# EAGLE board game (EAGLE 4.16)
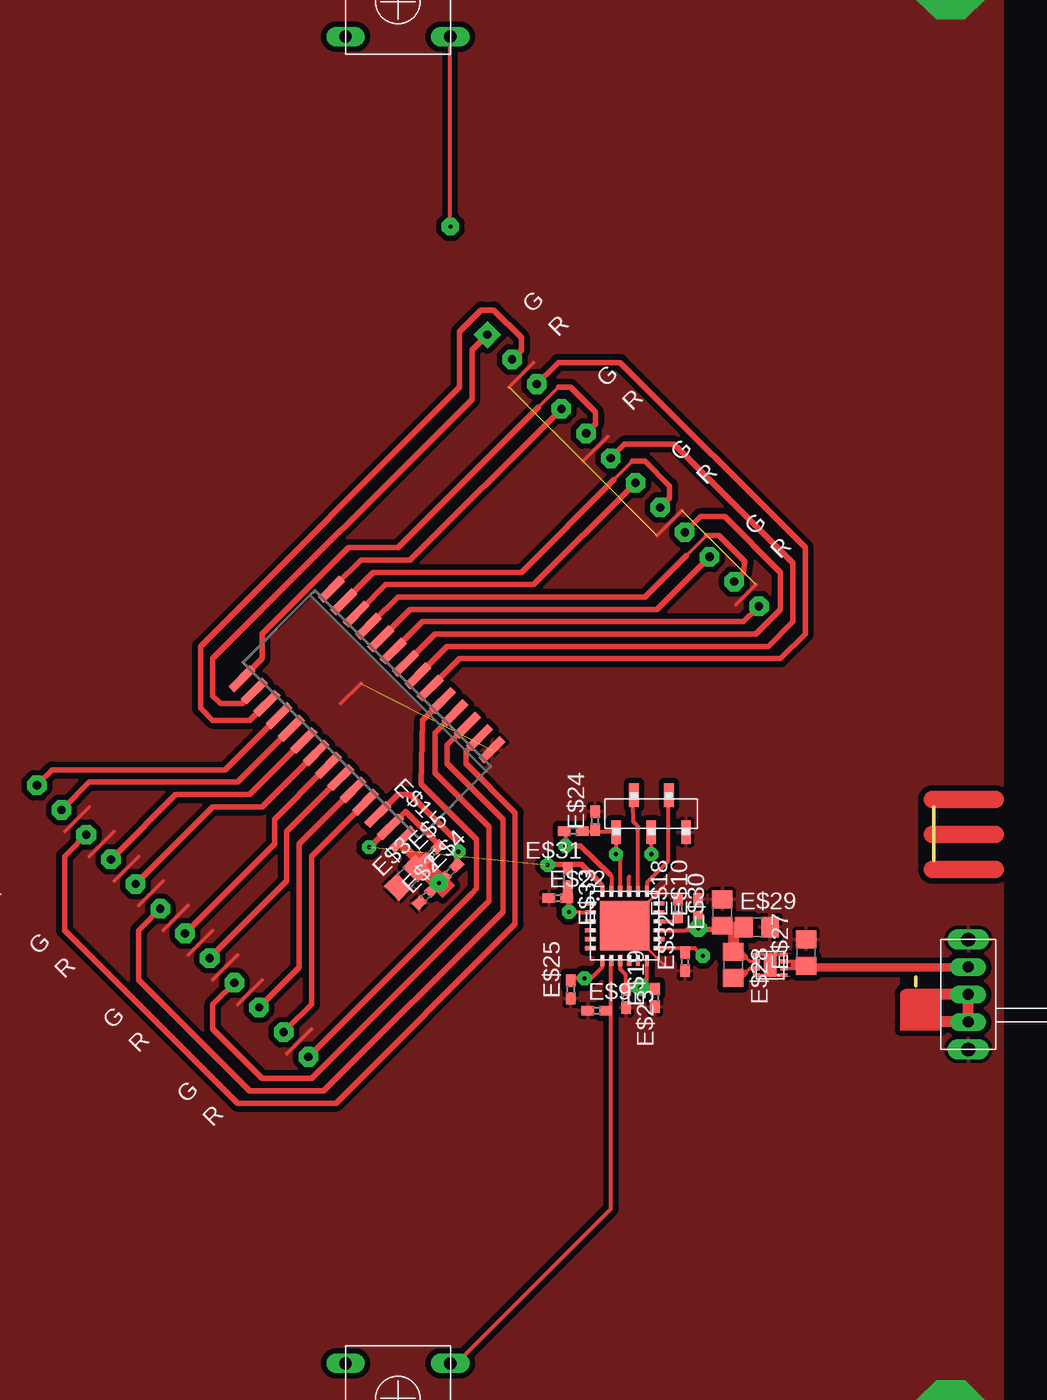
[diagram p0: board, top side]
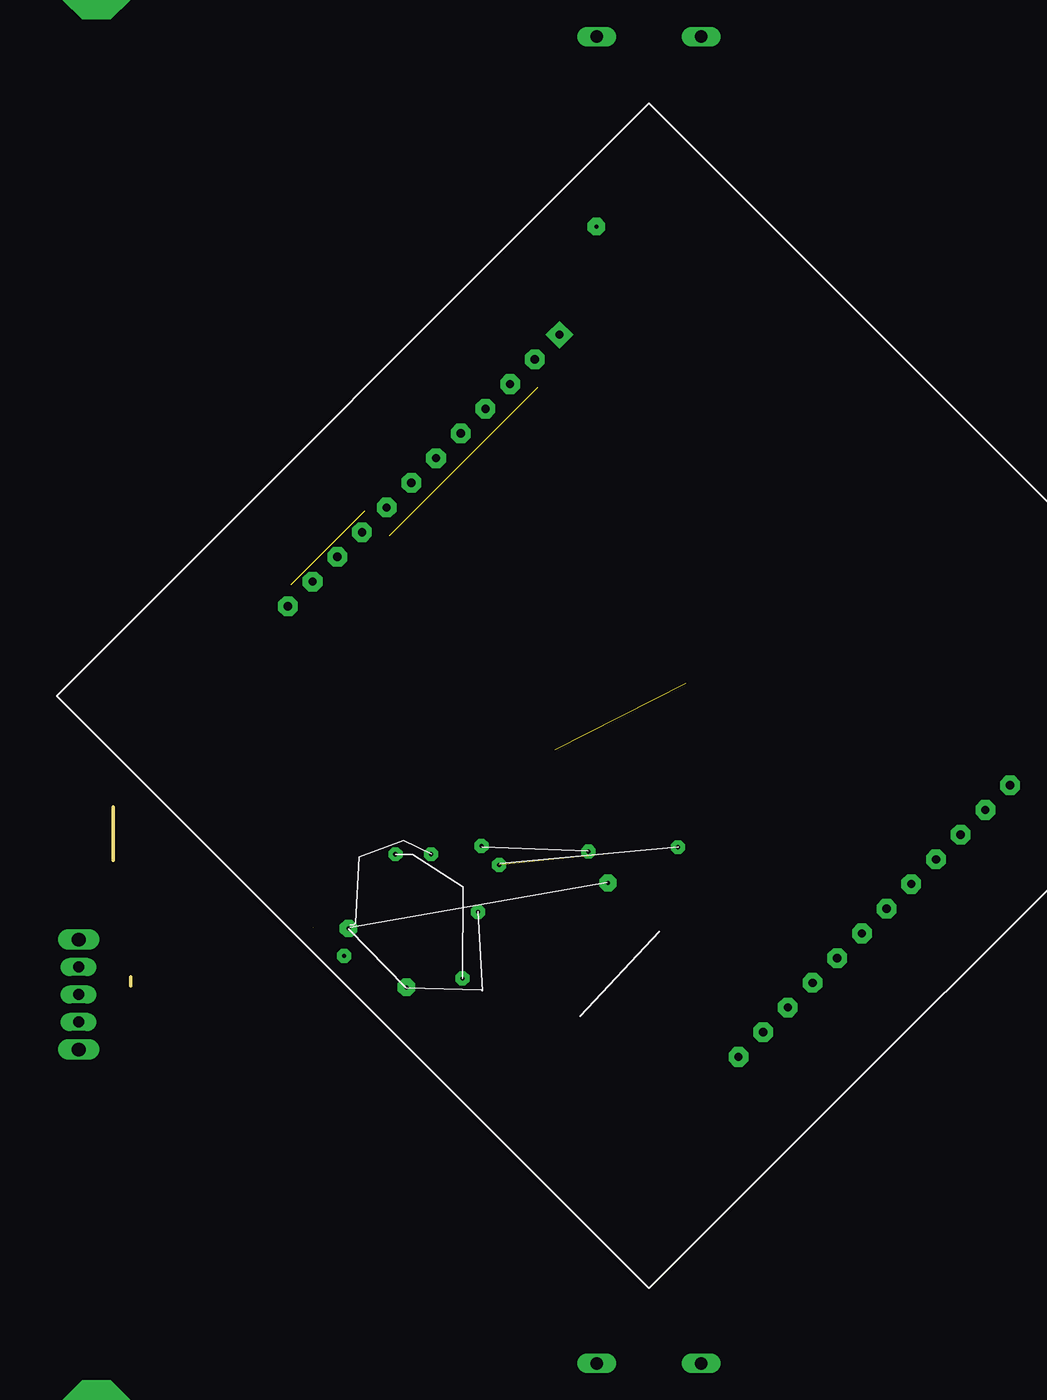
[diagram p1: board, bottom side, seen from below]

Size 1.3 x 13 mm. Coordinates in mm from the lower left corner, seen from the top.
Outline: 1.3,13 1.3,9.1
Outline: 0,0.65 0,0
Copper layers (1*16): Top 0.035mm / dielectric 1.5mm / Bottom 0.035mm
Design rules "default": minimum track width 10mil, minimum drill 24mil, track to track 8mil, track to pad 8mil, pad to pad 8mil, via to via 8mil, smd to smd 8mil, copper to edge 40mil, drill to drill 8mil, minimum pad ring 10mil, minimum via ring 8mil, stop-mask expansion 4mil, vias tented up to drill 0mil, thermal gap 10mil

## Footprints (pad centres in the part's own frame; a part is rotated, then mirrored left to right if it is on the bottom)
SO28W = smd 0.6 x 2.2: 1 -8.255,-4.6; 2 -6.985,-4.6; 3 -5.715,-4.6; 4 -4.445,-4.6; 5 -3.175,-4.6; 6 -1.905,-4.6; 7 -0.635,-4.6; 8 0.635,-4.6; 9 1.905,-4.6; 10 3.175,-4.6; 11 4.445,-4.6; 12 5.715,-4.6; 13 6.985,-4.6; 14 8.255,-4.6; 15 8.255,4.6; 16 6.985,4.6; 17 5.715,4.6; 18 4.445,4.6; 19 3.175,4.6; 20 1.905,4.6; 21 0.635,4.6; 22 -0.635,4.6; 23 -1.905,4.6; 24 -3.175,4.6; 25 -4.445,4.6; 26 -5.715,4.6; 27 -6.985,4.6; 28 -8.255,4.6
C0402 = smd 0.9 x 0.7: 1 -0.65,0; 2 0.65,0
C0805 = smd 1.3 x 1.5: 1 -0.95,0; 2 0.95,0
SW_TACT_KSL4 = drill 0.9 long: 1 -3.81,2.54; 2 -3.81,-2.54; 3 3.81,-2.54; 4 3.81,2.54
HEADER5S = smd 0.7 x 1.7: P$1 0,1.35; P$2 2.55,1.35; P$3 -2.55,1.35; P$4 -1.3,-1.35; P$5 1.25,-1.35
SLIDER6 = drill 1 long: P$1 -4,0; P$2 4,0 | drill 0.8 long: P$3 -2,0; P$4 0,0; P$5 2,0
LC2088AURYG1C = drill 0.6 pad 1.422 square: P$1 -13.97,-23.177 | drill 0.6 pad 1.422 octagon: P$2 -11.43,-23.177; P$3 -8.89,-23.177; P$4 -6.35,-23.177; P$5 -3.81,-23.177; P$6 -1.27,-23.177; P$7 1.27,-23.177; P$8 3.81,-23.177; P$9 6.35,-23.177; P$10 8.89,-23.177; P$11 11.43,-23.177; P$12 13.97,-23.177; P$13 -13.97,23.177; P$14 -11.43,23.177; P$15 -8.89,23.177; P$16 -6.35,23.177; P$17 -3.81,23.177; P$18 -1.27,23.177; P$19 1.27,23.177; P$20 3.81,23.177; P$21 6.35,23.177; P$22 8.89,23.177; P$23 11.43,23.177; P$24 13.97,23.177
QFN24-5 = smd 0.8 x 0.3: 1 -2.5,1.625; 2 -2.5,0.975; 3 -2.5,0.325; 4 -2.5,-0.325; 5 -2.5,-0.975; 6 -2.5,-1.625; 13 2.5,-1.625; 14 2.5,-0.975; 15 2.5,-0.325; 16 2.5,0.325; 17 2.5,0.975; 18 2.5,1.625 | smd 0.3 x 0.8: 7 -1.625,-2.5; 8 -0.975,-2.5; 9 -0.325,-2.5; 10 0.325,-2.5; 11 0.975,-2.5; 12 1.625,-2.5; 19 1.625,2.5; 20 0.975,2.5; 21 0.325,2.5; 22 -0.325,2.5; 23 -0.975,2.5; 24 -1.625,2.5 | smd 3.6 x 3.6: P$29 0,0
WSON8 = smd 0.28 x 0.5: 1 -1,-1; 2 -0.5,-1; 3 0,-1; 4 0.5,-1; 5 0.5,1; 6 0,1; 7 -0.5,1; 8 -1,1 | smd 1.6 x 0.9: EP -0.25,0

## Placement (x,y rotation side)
E$1  [SO28W]  not placed on the board
E$2  [C0402]  not placed on the board
E$3  [C0805]  not placed on the board
E$4  [C0402]  not placed on the board
E$5  [C0402]  not placed on the board
E$6  [SW_TACT_KSL4]  not placed on the board
E$7  [SW_TACT_KSL4]  not placed on the board
E$8  [HEADER5S]  not placed on the board
E$9  [C0402]  not placed on the board
E$10  [C0402]  not placed on the board
E$11  [SLIDER6]  3.8,-0.65 270 top
E$13  [LC2088AURYG1C]  not placed on the board
E$17  [QFN24-5]  not placed on the board
E$18  [C0402]  not placed on the board
E$19  [C0402]  not placed on the board
E$22  [C0402]  not placed on the board
E$23  [C0402]  not placed on the board
E$24  [C0402]  not placed on the board
E$25  [C0402]  not placed on the board
E$26  [WSON8]  -10.61,1.76 90 top  (outside the outline)
E$27  [C0805]  not placed on the board
E$28  [C0805]  not placed on the board
E$29  [C0805]  not placed on the board
E$30  [C0805]  not placed on the board
E$31  [C0402]  not placed on the board
E$32  [C0402]  not placed on the board
E$33  [C0402]  not placed on the board

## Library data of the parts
E$1-E$5 E$9 E$10 E$18 E$19 E$22-E$25 E$27-E$33 = ref-packages
E$6-E$8 E$11 = sb
E$13 = display-hp
E$17 = silabs
E$26 = texas

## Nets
GND: E$1.1 E$2.1 E$3.1 E$6.1 E$6.4 E$7.2 E$7.3 E$8.P$3 E$9.1 E$10.2 E$11.P$1 E$11.P$2 E$18.2 E$19.1 E$22.1 E$23.2 E$24.2 E$25.1 E$26.1 E$26.4 E$26.5 E$26.8 E$26.EP E$27.2 E$29.2 E$30.2 E$32.1
S$30: E$26.7
S$31: E$26.6
S$32: E$26.2
S$34: E$26.3
S$74: E$11.P$4

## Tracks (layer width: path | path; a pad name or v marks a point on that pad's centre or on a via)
GND  (via drill 0.5 pad 5)  (4 unrouted)
  Top 0.2: -20.22,5.33 -18.27,7.28 | -18.27,1.43 -20.14,3.3
  Top 0.254: -51.17,0.43 -49.37,2.23 | -58.35,7.62 -56.55,9.41 | -52.96,2.23 -51.17,4.03 | -56.55,5.82 -54.76,7.62 | -61.94,11.21 -60.15,13.01 | -60.15,9.41 -58.35,11.21 | -54.76,4.03 -52.96,5.82 | -49.37,-1.36 -47.57,0.43 | -45.78,-4.96 -43.98,-3.16 | -10.61,2.26 E$26.5 | -10.61,2.26 E$26.4 | -10.61,0.76 -10.61,2.26 | -10.61,0.76 E$26.1 | E$26.8 -10.61,0.76 | -41.85,20.53 -40.39,21.99 | -13.11,27.71 -11.65,29.17 | -29.61,43.54 -27.82,45.34 | -24.23,38.15 -22.43,39.95 | -18.84,32.76 -17.04,34.56
  other vias: -77.45,72.8 2.5,72.8 -77.45,-31.2 2.5,-31.2
  pour Top (isolate 0.406): 6.28,76.66 6.28,-35.1 -81.35,-35.1 -81.35,76.66
PWR
  Top 0.61: -7.85,1.5 -8.82,1.5
RST
  Top 0.3: -19.24,9.56 -19.24,11.28
S$1
  Top 0.406: -35,7.17 -34.67,7.51
  Top 0.61: -34.67,7.51 -37.58,10.42
S$2
  Top 0.406: -39.74,10.06 -38.59,11.21
S$3  (via drill 0.3 pad 1.27)
  other vias: -34.71,7.48
S$4
  Top 0.406: -27.82,43.54 -26.02,45.34 -21.53,45.34 -8.06,31.87 -8.06,25.58 -9.86,23.78 -33.21,23.78 -35.9,21.09
S$5
  Top 0.406: -36.8,21.99 -34.1,24.68 -10.76,24.68 -8.96,26.48 -8.96,30.74 -17.6,39.39 -21.2,39.39 -22.43,38.15
S$6
  Top 0.406: -17.04,32.76 -15.69,34.11 -13.9,34.11 -9.86,30.07 -9.86,27.37 -11.65,25.58 -35,25.58 -37.7,22.88
S$7
  Top 0.406: -11.65,27.37 -12.55,26.48 -35.9,26.48 -38.59,23.78
S$8
  Top 0.406: -32.31,17.5 -32.76,17.05 -32.76,16.15 -29.17,12.56 -29.17,4.48 -42.19,-8.55 -49.37,-8.55 -61.94,4.03 -61.94,9.41 -60.15,11.21
S$9
  Top 0.406: -33.21,18.39 -34.1,17.5 -34.1,16.15 -30.06,12.11 -30.06,5.37 -43.08,-7.65 -48.47,-7.65 -56.55,0.43 -56.55,4.03 -54.76,5.82
S$10
  Top 0.406: -34.1,19.29 -35,18.39 -35,15.48 -31.07,11.55 -31.07,6.16 -43.98,-6.75 -47.57,-6.75 -51.17,-3.16 -51.17,-1.36 -49.37,0.43
S$11
  Top 0.406: -35,20.19 -35.9,19.29 -36.01,14.69 -31.97,10.65 -31.97,7.06 -32.31,6.72 -43.98,-4.96
S$12
  Top 0.406: -40.39,13.01 -43.98,9.41 -43.98,-1.36 -45.78,-3.16
S$13
  Top 0.406: -41.29,13.9 -44.88,10.31 -44.88,1.33 -47.57,-1.36
S$14
  Top 0.406: -42.19,14.8 -45.78,11.21 -45.78,7.62 -51.17,2.23
S$15
  Top 0.406: -43.08,15.7 -46.68,12.11 -46.68,10.31 -52.96,4.03
S$16
  Top 0.406: -43.98,16.6 -47.57,13.01 -51.17,13.01 -56.55,7.62
S$17
  Top 0.406: -44.88,17.5 -48.47,13.9 -53.86,13.9 -58.35,9.41
S$18
  Top 0.406: -45.78,18.39 -49.37,14.8 -60.15,14.8 -61.94,13.01
S$19
  Top 0.406: -46.68,19.29 -50.27,15.7 -62.84,15.7 -63.74,14.8
S$20
  Top 0.406: -29.61,45.34 -28.72,46.23 -28.72,47.13 -30.74,49.15 -31.63,49.15 -33.21,47.58 -33.21,43.54 -52.06,24.68 -52.06,20.19 -51.17,19.29 -48.47,19.29 -47.57,20.19
S$21
  Top 0.254: -27.48,42.08 -26.02,43.54
  Top 0.406: -24.23,39.95 -23.33,40.84 -23.33,41.74 -25.12,43.54 -26.02,43.54 | -27.48,42.08 -37.7,31.87 -41.29,31.87 -47.57,25.58 -47.57,23.78 -48.47,22.88
S$22
  Top 0.406: -26.02,41.74 -36.8,30.97 -40.39,30.97 -42.19,29.17
S$23
  Top 0.406: -31.41,47.13 -32.31,46.23 -32.31,42.64 -51.17,23.78 -51.17,21.09 -50.61,20.53 -49.03,20.53 | -49.03,20.53 | -49.03,20.53 -48.47,21.09
S$24
  Top 0.406: -40.39,27.37 -38.59,29.17 -27.82,29.17 -20.63,36.35
S$25
  Top 0.254: -21.98,36.8 -20.63,38.15
  Top 0.406: -41.29,28.27 -39.49,30.07 -28.72,30.07 -21.98,36.8 | -20.63,38.15 -19.74,38.15 -17.94,36.35 -17.94,35.46 -18.84,34.56
S$26
  Top 0.254: -16.71,31.3 -15.25,32.76
  Top 0.406: -39.49,26.48 -37.7,28.27 -19.74,28.27 -16.71,31.3 | -15.25,32.76 -14.35,32.76 -12.44,30.85 -12.55,30.07 -13.45,29.17
S$27
  Top 0.406: -38.59,25.58 -36.8,27.37 -18.84,27.37 -15.25,30.97
S$28
  Top 0.406: -37.7,12.11 -37.13,12.67 -34.67,10.2
S$29
  Top 0.406: -38.59,13.01 -37.7,13.9 -36.8,13.9 -33.43,10.54 -33.43,8.74
S$30
  Top 0.254: E$26.7 -12.1,1.26 -12.4,0.96
  Top 0.406: -12.4,0.96 -13.16,0.2 -13.61,0.2
S$31
  Top 0.254: E$26.6 -12.1,1.76 -12.4,2.06
  Top 0.406: -12.4,2.06 -12.76,2.42 -13.61,2.42
S$32
  Top 0.254: E$26.2 -8.36,1.26
S$33
  Top 0.61: -8.22,1.36 -8.06,1.44
S$34
  Top 0.254: E$26.3 -8.37,1.76
S$35  (1 unrouted)
  Top 0.813: -13.26,2.35 -13.26,4.25 | -13.26,4.25 -14.05,4.25 | -13.26,4.25 -12.47,4.25
S$36
  Top 0.3: -19.57,6.63 -19.57,7.52 -18.02,9.08 -18.02,13.26
S$37
  Top 0.3: -18.92,4.03 -16.73,4.03
  Top 0.305: -16.73,4.03 -15.88,4.88
S$38
  Top 0.3: -18.92,4.68 -17.13,4.68
S$39
  Top 0.3: -19.57,2.08 -19.57,-0.11 -18.86,-0.11
S$40
  Top 0.3: -20.59,13.28 -20.57,11.94 -20.45,11.82 -20.22,11.58 -20.22,6.63
S$41
  Top 0.305: -25.26,5.36 -24.44,5.33 -23.47,5.33
S$42  (via drill 0.3 pad 1.02)
  other vias: -19.24,9.56
S$43  (via drill 0.3 pad 1.27)
  other vias: -33.87,55.22
S$44  (via drill 0.3 pad 1.27)
  other vias: -15.84,4.17
S$45  (via drill 0.3 pad 1.27)
  other vias: -20.06,-0.11
S$46
  Top 0.305: -23.89,8.4 -22.82,7.32 -22.82,7.28
S$47
  Top 0.305: -18.27,2.73 -16.11,2.73 -15.57,2.16
S$48
  Top 0.3: -21.52,2.08 -21.52,1.19 -21.11,0.78 -21.11,-0.11
  Top 0.305: -21.11,-0.11 -19.57,-0.11
S$49
  Top 0.406: -14.11,4.37 -14.11,4.49
S$50
  Top 0.406: -25.26,5.12 -25.26,6.42
S$51
  Top 0.305: -22.32,8.13 -22.32,8.12 -22.17,7.97 -22.17,7.28
  Top 0.406: -25.46,10.16 -24.41,10.16 -22.32,8.13
S$52
  Top 0.305: -24.04,0.54 -25.18,0.54
S$53
  Top 0.305: -20.87,6.63 -20.87,7.93
S$54
  Top 0.305: -24.14,11.22 -21.89,11.22
S$55
  Top 0.3: -21.52,6.63 -21.52,9.64
  Top 0.305: -21.52,9.64 -21.52,9.14
S$56
  Top 0.305: -21.79,9.27 -21.79,11.81
S$57
  Top 0.305: -25.27,6.13 -25.27,7.26
S$58
  Top 0.305: -22.2,1.95 -22.2,-16.25 -33.25,-27.3
S$59
  Top 0.406: -26.77,8.82 -24.34,8.82 -23.04,7.52
S$60
  Top 0.305: -25.48,10.16 -25.48,11.43
S$61
  Top 0.61: -8.01,1.32 3.74,1.33
S$62  (via drill 0.3 pad 1.02)  (1 unrouted)
  Top 0.406: v-25.26,5.35 v-25.26,5.36
S$63
  Top 0.406: -16.58,4.09 -13.98,4.09
S$64  (via drill 0.3 pad 1.02)
  other vias: -25.5,10.15
S$65  (via drill 0.3 pad 1.02)
  other vias: -33.3,9.75
S$66  (via drill 0.3 pad 1.02)  (1 unrouted)
  other vias: -39.8,10.07 -26.8,8.77
S$67  (via drill 0.3 pad 1.02)
  other vias: -21.84,9.56
S$68
  Top 0.305: -33.9,55.25 -33.9,68.9
S$69  (via drill 0.3 pad 1.02)
  Top 0.3: -22.82,2.08 -22.82,1.35 -23.63,0.54 -23.79,0.54 v-24.12,0.54
S$70  (via drill 0.3 pad 1.02)
  other vias: -15.51,2.16
S$71
  Top 1.27: 1.2,13.55 5.75,13.55
S$72
  Top 1.27: 1.2,11 5.75,11
S$73
  Top 1.27: 1.2,8.45 5.75,8.45
S$74
  Top 0.813: -0.75,-0.65 E$11.P$4 3.8,-2.6 -0.75,-2.6
(copper drawn outside any net)
  shapes: Top area x2

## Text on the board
tPlace: G | R | G | R | G | R | G | R | G | R | G | R | G | R | G | R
